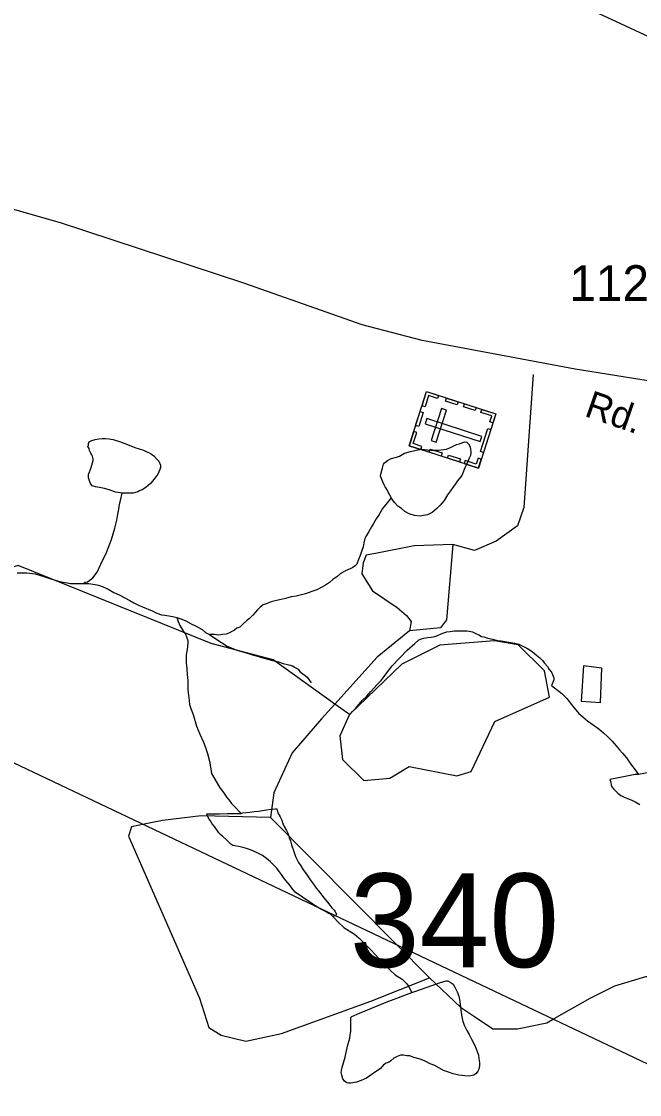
# Model space of a CAD drawing. Extents: x 2001466 to 2224147, y 644118 to 847247.
# Drawn here: x 2043867 to 2046028, y 665614 to 669371 of the extents above; entities that cross this region are included whole.
import ezdxf

# ---------------------------------------------------------------- set-up
doc = ezdxf.new("R2010")
doc.units = 0
for name, color, linetype in [('Exist Cultural Cemetery CELL', 7, 'Continuous'), ('Exist Hydrographic Misc Water Feature', 7, 'Continuous'), ('Exist Road Non-System Type 51', 7, 'Continuous'), ('Exist Road Secondary Structure Standard Bridge Number Label', 7, 'Continuous'), ('Exist Road Secondary Type 51 Attributed', 7, 'Continuous'), ('Exist Road Secondary Type 51 Label', 7, 'Continuous'), ('Exist Road Secondary Type 51 Number Label', 7, 'Continuous'), ('Exist Utilities Electrical Transmission Line', 7, 'Continuous')]:
    doc.layers.add(name, color=color, linetype=linetype)

msp = doc.modelspace()

# ---------------------------------------------------------------- linework, layer by layer
at = {"layer": 'Exist Cultural Cemetery CELL'}
for points in [[(2045222.5, 667885.4), (2045283.5, 668074.9), (2045525.9, 667996.8), (2045464.8, 667807.4)], [(2045324.8, 668061.7), (2045321.3, 668050.9), (2045290.7, 668060.8), (2045278.2, 668022.1), (2045267.7, 668025.6), (2045283.6, 668075)], [(2045390.9, 668028.4), (2045349.6, 668041.7), (2045353.1, 668052.5), (2045394.3, 668039.3)], [(2045299.7, 667903.4), (2045317.5, 667897.7), (2045353.6, 668009.7), (2045335.8, 668015.5)], [(2045453.6, 668008.2), (2045412.4, 668021.5), (2045415.9, 668032.3), (2045457.1, 668019)], [(2045515.7, 667965.3), (2045504.8, 667968.8), (2045511.5, 667989.8), (2045473.1, 668002.2), (2045476.5, 668012.8), (2045525.9, 667996.8)], [(2045245.2, 667955.9), (2045261.1, 668005.2), (2045271.9, 668001.7), (2045256, 667952.4)], [(2045283.8, 667980.2), (2045278, 667962.4), (2045471.1, 667900.3), (2045476.8, 667918)], [(2045263.7, 667872.1), (2045267.2, 667882.9), (2045236.5, 667892.8), (2045249, 667931.4), (2045238.4, 667934.8), (2045222.5, 667885.4)], [(2045471.5, 667865.6), (2045497.5, 667946.3), (2045508.4, 667942.8), (2045482.4, 667862.1)], [(2045334.3, 667849.4), (2045293, 667862.7), (2045296.5, 667873.5), (2045337.8, 667860.2)], [(2045398.2, 667828.8), (2045357, 667842), (2045360.5, 667852.9), (2045401.7, 667839.6)], [(2045474.9, 667838.8), (2045464, 667842.4), (2045457.2, 667821.4), (2045418.8, 667833.8), (2045415.4, 667823.2), (2045464.8, 667807.3)]]:
    msp.add_lwpolyline(points, close=True, dxfattribs=at)
at = {"layer": 'Exist Hydrographic Misc Water Feature'}
msp.add_line((2045013.3, 666943.9), (2044962.2, 666980.8), dxfattribs=at)
for points in [[(2046476.4, 668863.1), (2046176.4, 669262.9), (2045784.5, 669444.8), (2045475.5, 669693.8), (2045116.5, 669878.3), (2045081.2, 669887)], [(2044962.2, 666980.8), (2044746.4, 667136.4), (2044530.4, 667193.3), (2043854.4, 667466.2), (2043546.4, 667374), (2042521.3, 667663.9), (2042362.4, 667739.2), (2042229.3, 667879.8), (2041929.4, 668040.1), (2041828.5, 668212.8), (2041762.4, 668256.7), (2041570.5, 668306.6), (2041187.5, 668294.7), (2041120.4, 668328.9)], [(2044219.2, 667719.4), (2044205.2, 667721.4), (2044195.2, 667723.4), (2044177.1, 667729.3), (2044157.2, 667735.3), (2044139.2, 667739.3), (2044125.3, 667741.2), (2044113.2, 667745.2), (2044109.3, 667751.2), (2044105.2, 667759.2), (2044101.3, 667773.2), (2044101.1, 667785.2), (2044109.1, 667805.2), (2044113, 667817.2), (2044115, 667825.2), (2044117.1, 667833.2), (2044117.1, 667839.3), (2044115, 667849.3), (2044113, 667853.3), (2044108.9, 667859.1), (2044105, 667869.2), (2044102.9, 667875.2), (2044099, 667883.2), (2044100.9, 667887.2), (2044100.9, 667893.2), (2044102.9, 667899.2), (2044113, 667903.2), (2044124.8, 667907.2), (2044136.7, 667909.2), (2044148.8, 667911.2), (2044160.7, 667911.3), (2044172.8, 667909.3), (2044186.8, 667907.3), (2044213, 667899.3), (2044243, 667887.4), (2044262.8, 667879.5), (2044293, 667869.6), (2044302.8, 667865.6), (2044310.8, 667861.6), (2044320.9, 667855.6), (2044328.9, 667849.6), (2044338.9, 667839.6), (2044346.9, 667831.7), (2044353.1, 667817.7), (2044353.1, 667809.7), (2044351, 667801.7), (2044343, 667785.7), (2044333, 667771.6), (2044325, 667761.6), (2044317.2, 667753.6), (2044301.2, 667739.6), (2044289.1, 667731.6), (2044279.3, 667727.6), (2044273.1, 667723.6), (2044257.1, 667719.5), (2044239.3, 667719.5), (2044219.2, 667719.4)], [(2045159.1, 667703.2), (2045155, 667713.2), (2045149.1, 667723.2), (2045145, 667731.1), (2045139, 667741.1), (2045134.9, 667749.1), (2045130.8, 667759.1), (2045126.9, 667767.1), (2045122.8, 667779.1), (2045124.9, 667791.1), (2045129, 667807.1), (2045132.9, 667821.1), (2045136.8, 667825.1), (2045146.8, 667833.2), (2045156.9, 667839.2), (2045168.8, 667843.2), (2045178.8, 667845.2), (2045188.9, 667849.2), (2045206.7, 667859.2), (2045226.8, 667865.2), (2045252.6, 667871.3), (2045266.6, 667873.4), (2045286.7, 667871.4), (2045298.6, 667869.5), (2045324.6, 667869.5), (2045352.7, 667873.5), (2045366.6, 667879.5), (2045378.7, 667885.6), (2045388.6, 667889.6), (2045398.6, 667891.6), (2045406.6, 667895.6), (2045416.7, 667899.6), (2045424.7, 667897.6), (2045430.6, 667891.6), (2045434.7, 667883.7), (2045436.6, 667873.7), (2045438.6, 667863.7), (2045438.6, 667859.7), (2045436.6, 667851.7), (2045432.9, 667841.7), (2045422.8, 667819.6), (2045416.9, 667807.6), (2045406.8, 667781.6), (2045397, 667769.6), (2045390.8, 667761.6), (2045384.9, 667751.6), (2045374.8, 667739.6), (2045366.8, 667727.6), (2045357, 667713.6), (2045345.1, 667693.5), (2045331, 667677.5), (2045319.1, 667665.5), (2045303.1, 667651.4), (2045287.1, 667643.4), (2045273.1, 667641.4), (2045261.2, 667639.4), (2045241.2, 667641.4), (2045223.1, 667647.3), (2045207.1, 667655.3), (2045195.2, 667665.3), (2045183.1, 667673.3), (2045171, 667687.2), (2045159.1, 667703.2)], [(2044081.8, 667403.2), (2044089.8, 667407.2), (2044097.8, 667409.2), (2044105.8, 667415.3), (2044115.8, 667423.3), (2044131.6, 667443.3), (2044143.7, 667471.3), (2044163.6, 667511.4), (2044181.4, 667557.4), (2044193.3, 667597.4), (2044199.5, 667625.4), (2044203.4, 667645.4), (2044207.3, 667663.4), (2044209.3, 667681.4), (2044213.2, 667693.4), (2044219.2, 667719.4)], [(2045159.1, 667703.2), (2045145, 667685.2), (2045129.2, 667665.1), (2045117.1, 667645.1), (2045107.3, 667629.1), (2045097.2, 667613.1), (2045091.3, 667601.1), (2045081.2, 667585), (2045073.2, 667571), (2045067.3, 667561.1), (2045063.4, 667545.1), (2045061.3, 667531.1), (2045057.4, 667519), (2045051.5, 667501), (2045045.3, 667487), (2045039.6, 667471), (2045033.4, 667465), (2045025.4, 667459), (2045015.6, 667454.9), (2044999.6, 667446.9), (2044991.6, 667442.9), (2044981.6, 667436.9), (2044969.5, 667426.9), (2044955.7, 667416.9), (2044943.6, 667406.8)], [(2043851.7, 667440.8), (2043885.8, 667440.8), (2043913.9, 667436.9), (2043941.7, 667429), (2043965.7, 667421), (2043987.9, 667413.1), (2044005.7, 667409.1), (2044025.8, 667405.1), (2044037.7, 667403.2), (2044057.8, 667403.2), (2044071.7, 667403.2), (2044081.8, 667403.2)], [(2044081.8, 667403.2), (2044101.9, 667403.3), (2044123.8, 667399.3), (2044135.7, 667397.4), (2044151.7, 667391.4), (2044169.8, 667383.4), (2044189.9, 667371.4), (2044207.7, 667363.5), (2044245.8, 667343.5), (2044260, 667335.5), (2044276, 667327.6), (2044289.9, 667321.6), (2044324, 667307.7), (2044339.9, 667299.7), (2044355.9, 667293.7), (2044367.8, 667291.8), (2044382, 667289.8), (2044395.9, 667287.9), (2044409.9, 667283.9)], [(2044943.6, 667406.8), (2044929.7, 667396.8), (2044917.6, 667390.8), (2044899.7, 667380.8), (2044881.7, 667374.8), (2044859.6, 667366.7), (2044827.8, 667358.6), (2044809.7, 667356.6), (2044789.8, 667350.6), (2044753.7, 667342.5), (2044739.8, 667338.5), (2044721.8, 667332.4), (2044711.7, 667328.4), (2044701.9, 667320.4), (2044691.8, 667310.4), (2044675.8, 667292.4), (2044663.9, 667280.3), (2044653.9, 667272.3), (2044642, 667262.3), (2044630.1, 667250.3), (2044620, 667246.2), (2044612.1, 667240.2), (2044604.1, 667236.3), (2044594, 667230.3), (2044582.1, 667226.2), (2044570, 667224.2), (2044556.1, 667222.1), (2044541.9, 667224.1), (2044524.1, 667224)], [(2044409.9, 667283.9), (2044427.9, 667277.9), (2044441.9, 667271.9), (2044460.1, 667261.9), (2044477.9, 667254), (2044498, 667242), (2044509.9, 667232), (2044524.1, 667224)], [(2044409.9, 667283.9), (2044414, 667269.9), (2044420.1, 667255.9), (2044424, 667249.9), (2044436.1, 667231.9), (2044440, 667225.9), (2044444.1, 667215.9), (2044448, 667203.9), (2044448.2, 667193.9), (2044446.2, 667171.9), (2044442.1, 667153.9), (2044442.1, 667139.9), (2044442.3, 667125.9), (2044444.3, 667103.9), (2044446.4, 667084), (2044448.4, 667064), (2044448.4, 667044), (2044448.4, 667030), (2044450.5, 667012), (2044452.5, 666994), (2044454.6, 666980), (2044458.5, 666966), (2044466.5, 666944.1), (2044478.6, 666904.1), (2044490.7, 666876.1), (2044502.8, 666848.1), (2044508.7, 666832.1), (2044516.7, 666808.1), (2044524.9, 666776.2), (2044527, 666766.2), (2044528.8, 666754.2), (2044530.9, 666738.2)], [(2044524.1, 667224), (2044536, 667216.1), (2044566.1, 667196.2), (2044586.2, 667184.2), (2044620, 667170.2), (2044632.1, 667166.3), (2044652.2, 667160.3), (2044664.1, 667156.4), (2044678.1, 667152.4), (2044692.2, 667148.4), (2044706.2, 667144.4), (2044720.1, 667140.5), (2044740.2, 667134.5), (2044766, 667128.5), (2044782.2, 667122.5), (2044802.1, 667118.6), (2044814.2, 667114.6), (2044824.1, 667108.7), (2044834.1, 667102.7), (2044840.3, 667094.7), (2044850.3, 667086.8), (2044858.3, 667080.8), (2044866.3, 667074.8), (2044880.3, 667054.8)], [(2045016.4, 666945.1), (2045024.4, 666955.1), (2045036.3, 666967.1), (2045046.4, 666979.1), (2045058.5, 666993.1), (2045074.2, 667009.2), (2045088.2, 667025.2), (2045110.3, 667049.2), (2045124.3, 667063.2), (2045162.2, 667113.3), (2045190.1, 667143.3), (2045215.9, 667169.4), (2045242, 667193.4), (2045255.9, 667205.4), (2045266, 667209.4), (2045274, 667211.5), (2045287.9, 667213.5), (2045299.8, 667215.5), (2045311.9, 667217.6), (2045321.9, 667221.6), (2045332, 667225.6), (2045340, 667229.6), (2045353.9, 667233.6), (2045365.8, 667235.6), (2045380, 667237.7), (2045391.9, 667237.7), (2045404, 667237.7), (2045415.9, 667237.8), (2045423.9, 667237.8), (2045431.9, 667235.8), (2045443.9, 667233.8), (2045455.8, 667227.8), (2045465.9, 667223.8), (2045475.9, 667217.9), (2045483.9, 667215.9), (2045497.9, 667211.9), (2045513.9, 667208), (2045531.9, 667204), (2045543.8, 667202), (2045577.8, 667196.1), (2045591.8, 667194.1), (2045605.9, 667190.2), (2045616, 667186.2), (2045635.9, 667176.1), (2045641.8, 667172.2), (2045653.9, 667164.2), (2045667.9, 667152.3), (2045680, 667142.3), (2045688, 667134.3), (2045696, 667124.3), (2045706, 667112.3), (2045712, 667102.4), (2045719.9, 667092.4), (2045724, 667084.4), (2045728.2, 667072.4), (2045728.2, 667066.4), (2045726.1, 667060.3), (2045724, 667054.3), (2045720.2, 667046.3)], [(2045013.3, 666943.9), (2044980.3, 666869.2), (2044989.3, 666786.9), (2045064.4, 666713.3), (2045155.4, 666721.3), (2045222.3, 666762.6), (2045389.4, 666729.6), (2045439.4, 666745), (2045522.5, 666920.5), (2045713.4, 667005.2), (2045696.4, 667097.4), (2045604.3, 667187.8), (2045521.5, 667202.7), (2045330.3, 667186.9), (2045196.5, 667120.7), (2045013.3, 666943.9)], [(2045832.1, 667114.5), (2045824.3, 666990.6), (2045892.2, 666986.7), (2045896.1, 667106.7), (2045832.1, 667114.5)], [(2045720.2, 667046.3), (2045756, 667018.4), (2045774.3, 667000.4), (2045794.2, 666974.5), (2045816.3, 666948.5), (2045830.3, 666936.6), (2045846.5, 666922.6), (2045866.4, 666908.6), (2045886.5, 666894.7), (2045902.4, 666880.7), (2045918.4, 666864.8), (2045932.6, 666850.8), (2045946.5, 666834.9), (2045958.4, 666820.8), (2045968.5, 666808.8), (2045982.4, 666792.9), (2046000.7, 666766.9), (2046012.6, 666750.9), (2046024.7, 666734.9)], [(2044530.9, 666738.2), (2044558.9, 666690.2), (2044574.9, 666668.3), (2044585, 666654.3), (2044593.2, 666644.3), (2044601.2, 666632.3), (2044611.2, 666622.4), (2044635.2, 666598.4)], [(2046024.7, 666734.9), (2046012.6, 666734.9), (2045954.5, 666722.9), (2045924.8, 666716.8), (2045926.8, 666710.8), (2045930.7, 666692.9), (2045938.7, 666682.8), (2045952.7, 666668.8), (2045962.7, 666660.9), (2045974.8, 666654.9), (2045986.7, 666650.9), (2046000.9, 666645), (2046014.8, 666637), (2046029, 666629)], [(2046080.6, 666745.1), (2046024.7, 666734.9)], [(2044947.7, 666245.1), (2044939.7, 666249.1), (2044929.7, 666255), (2044917.8, 666261), (2044907.7, 666267), (2044895.8, 666272.9), (2044885.6, 666281), (2044873.7, 666288.9), (2044861.6, 666296.9), (2044849.7, 666304.9), (2044841.7, 666310.8), (2044831.7, 666316.8), (2044823.7, 666322.8), (2044813.6, 666334.8), (2044805.6, 666346.7), (2044797.6, 666354.7), (2044785.5, 666370.7), (2044775.5, 666384.7), (2044765.4, 666398.7), (2044759.5, 666406.7), (2044751.5, 666414.7), (2044737.5, 666428.6), (2044723.4, 666440.6), (2044709.5, 666450.5), (2044691.4, 666460.5), (2044667.4, 666470.5), (2044657.4, 666474.5), (2044641.4, 666478.4), (2044625.4, 666482.4), (2044613.3, 666484.4), (2044605.3, 666486.4), (2044599.3, 666490.4), (2044587.4, 666502.3), (2044569.2, 666518.3), (2044565.3, 666522.3), (2044557.3, 666530.3), (2044549.3, 666540.3), (2044541.3, 666552.2), (2044533.3, 666562.2), (2044527.2, 666572.2), (2044523.3, 666578.2), (2044517.1, 666588.2), (2044515.1, 666596.2), (2044559.1, 666596.2), (2044587, 666598.3), (2044613.1, 666598.4), (2044635.2, 666598.4)], [(2044635.2, 666598.4), (2044641.2, 666600.4), (2044665.2, 666602.4), (2044681.2, 666604.5), (2044695.1, 666606.5), (2044723.2, 666610.6), (2044739.2, 666612.6), (2044755.2, 666614.6), (2044759.1, 666614.6), (2044763.2, 666600.6), (2044771.2, 666586.7), (2044777.1, 666574.7), (2044781.2, 666562.7), (2044785.3, 666552.7), (2044793.3, 666538.7), (2044799.3, 666526.8), (2044803.2, 666512.8), (2044807.3, 666502.7), (2044811.4, 666488.7), (2044819.4, 666464.7), (2044825.3, 666446.8), (2044835.4, 666426.8), (2044843.6, 666414.8), (2044851.6, 666400.9), (2044863.4, 666384.9), (2044877.6, 666364.9), (2044887.4, 666350.9), (2044897.7, 666336.9), (2044905.7, 666326.9), (2044925.6, 666301), (2044941.6, 666281.1), (2044951.8, 666267.1), (2044959.8, 666259.1), (2044963.7, 666253.1), (2044965.8, 666249.1), (2044967.8, 666245.1), (2044965.8, 666241.1), (2044955.8, 666237.1), (2044947.7, 666245.1)], [(2044947.7, 666245.1), (2044955.8, 666237.1), (2044959.8, 666233.1), (2044973.8, 666217.1), (2044993.9, 666199.1)], [(2044993.9, 666199.1), (2045031.8, 666175.2), (2045047.8, 666161.3), (2045067.9, 666141.3), (2045085.9, 666123.3), (2045106, 666101.4), (2045124.1, 666081.4), (2045138, 666069.5), (2045156.1, 666049.5), (2045174.1, 666033.5), (2045198.1, 666017.6)], [(2045198.1, 666017.6), (2045208.1, 666007.6), (2045214.1, 666001.6), (2045220, 665993.6), (2045232.1, 665971.6)], [(2045232.1, 665971.6), (2045246.1, 665975.6), (2045302.1, 665995.7), (2045332.2, 666005.8), (2045352.1, 666011.8), (2045358, 666011.9), (2045366, 666007.9), (2045376.1, 665999.9), (2045382, 665989.9), (2045390, 665973.9), (2045396.2, 665958), (2045400.3, 665940), (2045402.3, 665920), (2045404.2, 665902), (2045406.4, 665885.9), (2045410.3, 665870), (2045416.3, 665854), (2045424.3, 665838), (2045432.3, 665824), (2045440.5, 665808.1), (2045450.5, 665788.1), (2045456.5, 665774.1), (2045460.6, 665764.1), (2045464.5, 665752.1), (2045466.5, 665740.1), (2045468.6, 665726.1), (2045468.6, 665714.1), (2045466.5, 665702.2), (2045462.6, 665696.2), (2045456.7, 665688.1), (2045448.7, 665682.1), (2045442.7, 665680.1), (2045432.7, 665678.1), (2045416.7, 665680), (2045396.8, 665682), (2045376.7, 665686), (2045356.6, 665693.9), (2045342.7, 665697.9), (2045312.5, 665715.8), (2045296.5, 665721.8), (2045276.6, 665731.8), (2045260.6, 665737.7), (2045238.7, 665743.7), (2045224.5, 665749.6), (2045214.7, 665749.6), (2045202.6, 665751.6), (2045192.6, 665751.6), (2045180.7, 665747.6), (2045168.6, 665741.6), (2045158.5, 665731.5), (2045152.6, 665727.5), (2045142.5, 665723.5), (2045132.7, 665717.5), (2045122.6, 665705.5), (2045110.7, 665697.4), (2045100.7, 665691.4), (2045084.7, 665679.4), (2045072.8, 665671.4), (2045064.8, 665667.4), (2045054.8, 665663.4), (2045038.8, 665657.3), (2045018.9, 665653.3), (2045010.9, 665653.2), (2045004.9, 665655.2), (2045000.8, 665657.2), (2044996.7, 665661.2), (2044990.8, 665669.2), (2044986.7, 665681.2), (2044984.6, 665691.2), (2044986.7, 665705.2), (2044998.6, 665745.3), (2045006.6, 665783.3), (2045014.6, 665811.2), (2045016.4, 665823.2), (2045018.5, 665835.2), (2045018.5, 665847.3), (2045018.5, 665861.3), (2045018.3, 665875.3), (2045018.3, 665883.3), (2045022.4, 665887.3), (2045048.4, 665899.3), (2045142.3, 665937.5), (2045232.1, 665971.6)]]:
    msp.add_lwpolyline(points, dxfattribs=at)
at = {"layer": 'Exist Road Non-System Type 51'}
for p, q in [((2045173.5, 666143.8), (2044737.9, 666583.8)), ((2045294.1, 666022), (2045173.5, 666143.8))]:
    msp.add_line(p, q, dxfattribs=at)
for points in [[(2045655.9, 668134.3), (2045623.5, 667669.7), (2045601.9, 667604.9), (2045526.3, 667550.9), (2045450.7, 667518.5), (2045375.1, 667540.1)], [(2045375.1, 667540.1), (2045240.1, 667534.7), (2045105.1, 667507.7), (2045072.7, 667502.3), (2045061.9, 667475.2), (2045056.5, 667437.4), (2045094.3, 667378), (2045180.7, 667318.6), (2045213.1, 667291.6), (2045229.3, 667270), (2045223.9, 667237.5)], [(2045375.1, 667540.1), (2045353.5, 667275.4), (2045331.9, 667248.3), (2045223.9, 667237.5)], [(2045223.9, 667237.5), (2045110.5, 667145.7), (2044962.2, 666980.8)], [(2044962.2, 666980.8), (2044916.1, 666929.6), (2044813.5, 666810.7), (2044748.7, 666670.3), (2044737.9, 666583.8)], [(2044737.9, 666583.8), (2044494.9, 666589.2), (2044359.9, 666573), (2044296.2, 666560.3)], [(2044296.2, 666560.3), (2044251.9, 666551.4), (2044241.1, 666519), (2044489.5, 665951.8), (2044521.9, 665849.1), (2044565.1, 665822.1), (2044651.5, 665800.5), (2044775.7, 665827.5), (2045088.9, 665941), (2045294.1, 666022)], [(2045294.1, 666022), (2045402.1, 665919.3), (2045450.7, 665886.9), (2045515.5, 665843.7), (2045601.9, 665843.7), (2045704.5, 665865.3), (2045729.8, 665879.7)], [(2045729.8, 665879.7), (2045855.7, 665951.8), (2045942.1, 665995), (2046050.1, 666027.4), (2046136.5, 666027.4), (2046206.7, 665995), (2046255.3, 665919.3), (2046298.5, 665908.5), (2046357.9, 665919.3), (2046428.1, 665984.2), (2046460.5, 666011.2), (2046622.5, 665984.2)]]:
    msp.add_lwpolyline(points, dxfattribs=at)
at = {"layer": 'Exist Road Secondary Type 51 Attributed'}
msp.add_lwpolyline([(2047420.9, 668051.6), (2046969, 668061), (2046413.8, 668075.8), (2046167.8, 668094.8), (2045802.6, 668154), (2045268.5, 668253.3), (2045058.4, 668308.2), (2044644.6, 668454), (2044002.8, 668665.3), (2043102.4, 668923), (2042428.9, 669113.1), (2041642.5, 669316), (2041375.5, 669363.9), (2040930.6, 669438.5), (2040675.4, 669476.9), (2040612.2, 669494.4), (2040566.4, 669515.2)], dxfattribs=at)
at = {"layer": 'Exist Utilities Electrical Transmission Line'}
msp.add_lwpolyline([(2049560.3, 664054.6), (2040710.9, 668262.4), (2038924.4, 668808.4)], dxfattribs=at)

# ---------------------------------------------------------------- texts
at = {"layer": 'Exist Road Secondary Structure Standard Bridge Number Label'}
msp.add_text('340', height=328.08, dxfattribs=at).set_placement((2045015, 666059.8))
at = {"layer": 'Exist Road Secondary Type 51 Label'}
msp.add_text('Rd.', height=95, rotation=340.8832, dxfattribs=at).set_placement((2045831.7, 667990.5))
at = {"layer": 'Exist Road Secondary Type 51 Number Label'}
msp.add_text('1123', height=125, dxfattribs=at).set_placement((2045782.6, 668392.4))

doc.saveas('drawing.dxf')
